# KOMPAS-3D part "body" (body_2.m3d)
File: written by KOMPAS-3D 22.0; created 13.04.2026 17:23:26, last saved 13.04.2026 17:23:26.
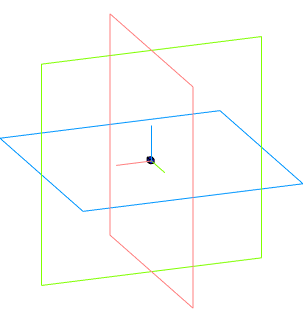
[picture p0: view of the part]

Document properties: Автор: Andrey; Полное имя файла: C:\Users\User1\Documents\body_2.m3d

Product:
- Part/product: body

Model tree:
1. Операция без истории:1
